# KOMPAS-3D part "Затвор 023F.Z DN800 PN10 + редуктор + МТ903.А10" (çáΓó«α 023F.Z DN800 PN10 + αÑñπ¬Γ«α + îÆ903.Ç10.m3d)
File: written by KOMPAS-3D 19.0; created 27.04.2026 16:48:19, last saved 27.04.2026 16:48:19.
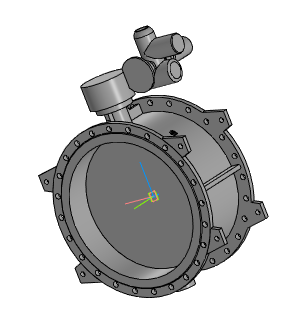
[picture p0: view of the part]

Document properties: Полное имя файла: ..\..\Затвор 023F.Z DN400-DN1600 + редуктор + МТ903\Затвор 023F.Z DN800 PN10 + редуктор + МТ903.А10.a3d

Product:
- Part/product: Затвор 023F.Z DN800 PN10 + редуктор + МТ903.А10
    Масса: 823.913

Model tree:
1. Операция без истории:1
